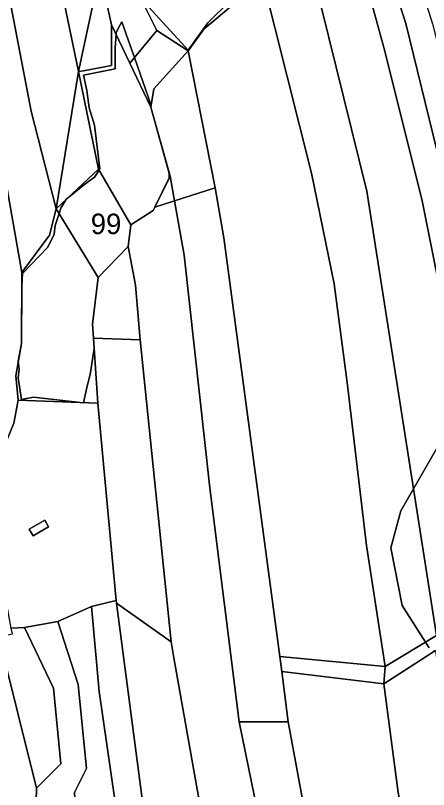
# Model space of a CAD drawing. Extents: x -502026 to -497664, y -1143484 to -1138019.
# Drawn here: x -499381.8 to -499220.8, y -1140133.9 to -1139831.7 of the extents above; entities that cross this region are included whole.
import ezdxf

# ---------------------------------------------------------------- set-up
doc = ezdxf.new("R2010")
doc.units = 0
for name, color, linetype in [('25', 7, 'Continuous'), ('31', 7, 'Continuous'), ('37', 7, 'Continuous'), ('43', 7, 'Continuous'), ('55', 7, 'Continuous'), ('62', 7, 'Continuous'), ('7', 7, 'Continuous')]:
    doc.layers.add(name, color=color, linetype=linetype)

msp = doc.modelspace()

# ---------------------------------------------------------------- linework, layer by layer
at = {"layer": '25'}
msp.add_lwpolyline([(-499275.49, -1140107.46), (-499268.89, -1140143.37), (-499257.79, -1140186.68), (-499277.97, -1140188.93), (-499294.52, -1140107.43)], close=True, dxfattribs=at)
at = {"layer": '31'}
for points in [[(-499349.66, -1139983.08), (-499342.49, -1140060.03), (-499352.11, -1140062.42), (-499365.32, -1140068.27), (-499378.26, -1140070.59), (-499383.4, -1140070.89), (-499393.27, -1140017.22), (-499382.43, -1139990.82), (-499380.68, -1139981.87)], [(-499368.86, -1140031.32), (-499370.36, -1140028.72), (-499376.42, -1140032.22), (-499374.92, -1140034.82)]]:
    msp.add_lwpolyline(points, close=True, dxfattribs=at)
at = {"layer": '37'}
for points in [[(-499303.92, -1139898.93), (-499319.81, -1139904.04), (-499321.51, -1139894.4), (-499328.94, -1139867.55), (-499327.8, -1139860.27), (-499314.46, -1139845.56)], [(-499319.81, -1139904.04), (-499327.5, -1139906.51), (-499321.51, -1139894.4)], [(-499333.13, -1139958.35), (-499351.39, -1139957.72), (-499351.77, -1139952.17), (-499349.52, -1139933.94), (-499337.88, -1139921.84), (-499334.94, -1139937)], [(-499333.13, -1139958.35), (-499321.12, -1140076.23), (-499342.35, -1140061.12), (-499342.49, -1140060.03), (-499349.66, -1139983.08), (-499351.39, -1139957.72)], [(-499175.16, -1140286.65), (-499173.86, -1140291.43), (-499164.43, -1140325.93), (-499181.73, -1140330.12), (-499177.24, -1140351.2), (-499198.42, -1140279.37), (-499205.65, -1140254.74), (-499215.6, -1140225.13), (-499224.19, -1140180), (-499232.57, -1140135.07), (-499238.14, -1140092.65), (-499218.01, -1140079.54), (-499208.2, -1140152.9), (-499200.42, -1140191.86), (-499195.81, -1140212.12), (-499192.03, -1140228.73), (-499184.85, -1140253.13)], [(-499238.14, -1140092.65), (-499232.57, -1140135.07), (-499224.19, -1140180), (-499215.6, -1140225.13), (-499205.65, -1140254.74), (-499198.42, -1140279.37), (-499177.24, -1140351.2), (-499181.86, -1140350.58), (-499186.12, -1140330.89), (-499194.15, -1140301.4), (-499232.59, -1140308.74), (-499240.39, -1140276.46), (-499257.79, -1140186.68), (-499268.89, -1140143.37), (-499275.49, -1140107.46), (-499277.96, -1140087.8)]]:
    msp.add_lwpolyline(points, close=True, dxfattribs=at)
at = {"layer": '43'}
msp.add_lwpolyline([(-499285.35, -1139817.65), (-499308.24, -1139836.91), (-499314.46, -1139845.56), (-499326.63, -1139837.6), (-499334.36, -1139822.12)], dxfattribs=at)
for points in [[(-499337.17, -1139850.27), (-499328.94, -1139867.55), (-499321.51, -1139894.4), (-499327.5, -1139906.51), (-499328.13, -1139907.79), (-499336.82, -1139913.47), (-499349.41, -1139891.67), (-499357.18, -1139853.6), (-499355.29, -1139853.26), (-499344.29, -1139851.25), (-499344.29, -1139835.32)], [(-499336.82, -1139913.47), (-499337.88, -1139921.84), (-499349.52, -1139933.94), (-499365.9, -1139907.16), (-499349.41, -1139891.67)], [(-499349.52, -1139933.94), (-499351.77, -1139952.17), (-499351.39, -1139957.72), (-499349.66, -1139983.08), (-499380.68, -1139981.87), (-499381.67, -1139972.31), (-499379.47, -1139959.8), (-499379.32, -1139932.04), (-499368.48, -1139917.4), (-499365.9, -1139907.16)], [(-499357.37, -1140158.51), (-499365.32, -1140171.39), (-499369.48, -1140189.57), (-499363.93, -1140210.02), (-499359.89, -1140229.53), (-499370.27, -1140214.75), (-499371, -1140201.82), (-499375.55, -1140186.57), (-499378.31, -1140154.18), (-499373.9, -1140148.81), (-499373.55, -1140133.33), (-499364.06, -1140123.86), (-499366.96, -1140094.25), (-499378.26, -1140070.59), (-499365.32, -1140068.27), (-499357.31, -1140092.81), (-499354.09, -1140125.66), (-499358.76, -1140135)]]:
    msp.add_lwpolyline(points, close=True, dxfattribs=at)
at = {"layer": '55'}
for points in [[(-499335.19, -1139789.66), (-499331.93, -1139812.11), (-499334.36, -1139822.12), (-499326.63, -1139837.6), (-499337.17, -1139850.27), (-499344.29, -1139835.32), (-499348.85, -1139814.64), (-499339.35, -1139770.23)], [(-499344.29, -1139835.32), (-499344.29, -1139851.25), (-499355.29, -1139853.26), (-499357.18, -1139853.6), (-499348.85, -1139814.64)], [(-499314.46, -1139845.56), (-499327.8, -1139860.27), (-499328.94, -1139867.55), (-499337.17, -1139850.27), (-499326.63, -1139837.6)], [(-499349.41, -1139891.67), (-499365.9, -1139907.16), (-499357.18, -1139853.6)], [(-499368.86, -1140031.32), (-499374.92, -1140034.82), (-499376.42, -1140032.22), (-499370.36, -1140028.72)], [(-499237.69, -1140085.86), (-499238.14, -1140092.65), (-499277.96, -1140087.8), (-499278.75, -1140081.89)]]:
    msp.add_lwpolyline(points, close=True, dxfattribs=at)
msp.add_lwpolyline([(-499218.01, -1140079.54), (-499238.14, -1140092.65), (-499237.69, -1140085.86), (-499217.66, -1140073.7)], dxfattribs=at)
at = {"layer": '62'}
for points in [[(-499332.69, -1139825.25), (-499314.44, -1139845.25), (-499306.78, -1139834.62), (-499289.78, -1139817.62)], [(-499289.78, -1139817.62), (-499306.78, -1139834.62), (-499314.44, -1139845.25), (-499332.69, -1139825.25)], [(-499220.5, -1140078.5), (-499221.91, -1140076.28), (-499231, -1140062), (-499235.5, -1140039.5), (-499231.5, -1140025), (-499226.61, -1140016.51), (-499217.09, -1140000)], [(-499217.09, -1140000), (-499226.61, -1140016.51), (-499231.5, -1140025), (-499235.5, -1140039.5), (-499231, -1140062), (-499221.91, -1140076.28), (-499220.5, -1140078.5)]]:
    msp.add_lwpolyline(points, dxfattribs=at)
for points in [[(-499337.1, -1139843.35), (-499340.34, -1139834.12), (-499340.98, -1139835.39), (-499342.47, -1139838.37), (-499342.52, -1139839.04), (-499342.91, -1139844.37), (-499342.91, -1139852.5), (-499355.22, -1139855), (-499353.94, -1139861), (-499353.58, -1139863.89), (-499353.09, -1139867.75), (-499350.97, -1139874.5), (-499348.84, -1139891.5), (-499349.19, -1139892.05), (-499350.97, -1139894.87), (-499354.78, -1139897.5), (-499361.03, -1139902.59), (-499361.54, -1139903), (-499362, -1139903.37), (-499362.17, -1139903.66), (-499364.12, -1139906.87), (-499364.79, -1139908.98), (-499366.25, -1139913.62), (-499366.69, -1139917), (-499369.22, -1139922.12), (-499379, -1139932.37), (-499379.35, -1139936.94), (-499379.47, -1139959.8), (-499380.67, -1139966.63), (-499380.28, -1139969.75), (-499380.72, -1139973.12), (-499379.44, -1139981.62), (-499374.75, -1139980.75), (-499355.39, -1139982.86), (-499355.29, -1139982.86), (-499355.22, -1139982.86), (-499353.94, -1139976.87), (-499352.66, -1139971.87), (-499351.81, -1139966.75), (-499351.11, -1139961.76), (-499351.39, -1139957.72), (-499351.77, -1139952.17), (-499349.52, -1139933.94), (-499337.88, -1139921.84), (-499336.82, -1139913.47), (-499328.13, -1139907.79), (-499327.5, -1139906.51), (-499321.83, -1139895.05), (-499321.9, -1139893.66), (-499321.94, -1139892.85), (-499328.94, -1139867.55), (-499328.83, -1139866.84), (-499335.41, -1139848.15)], [(-499353.94, -1139976.87), (-499355.22, -1139982.86), (-499355.29, -1139982.86), (-499355.39, -1139982.86), (-499374.75, -1139980.75), (-499379.44, -1139981.62), (-499380.72, -1139973.12), (-499380.28, -1139969.75), (-499380.67, -1139966.63), (-499379.47, -1139959.8), (-499379.35, -1139936.94), (-499379, -1139932.37), (-499369.22, -1139922.12), (-499366.69, -1139917), (-499366.25, -1139913.62), (-499364.79, -1139908.98), (-499364.12, -1139906.87), (-499362.17, -1139903.66), (-499362, -1139903.37), (-499361.54, -1139903), (-499361.03, -1139902.59), (-499354.78, -1139897.5), (-499350.97, -1139894.87), (-499349.19, -1139892.05), (-499348.84, -1139891.5), (-499350.97, -1139874.5), (-499353.09, -1139867.75), (-499353.58, -1139863.89), (-499353.94, -1139861), (-499355.22, -1139855), (-499342.91, -1139852.5), (-499342.91, -1139844.37), (-499342.52, -1139839.04), (-499342.47, -1139838.37), (-499340.98, -1139835.39), (-499340.34, -1139834.12), (-499337.1, -1139843.35), (-499335.41, -1139848.15), (-499328.83, -1139866.84), (-499328.94, -1139867.55), (-499321.94, -1139892.85), (-499321.9, -1139893.66), (-499321.83, -1139895.05), (-499327.5, -1139906.51), (-499328.13, -1139907.79), (-499336.82, -1139913.47), (-499337.88, -1139921.84), (-499349.52, -1139933.94), (-499351.77, -1139952.17), (-499351.39, -1139957.72), (-499351.11, -1139961.76), (-499351.81, -1139966.75), (-499352.66, -1139971.87)]]:
    msp.add_lwpolyline(points, close=True, dxfattribs=at)
at = {"layer": '7'}
for points in [[(-499462.13, -1139392.32), (-499452.18, -1139431.77), (-499430, -1139542.05), (-499408.7, -1139631.01), (-499398.52, -1139677.52), (-499366.99, -1139806.44), (-499357.18, -1139853.6), (-499365.9, -1139907.16), (-499375.64, -1139869.1), (-499386.86, -1139810.63), (-499402.82, -1139746.67), (-499404.07, -1139741.68), (-499434.09, -1139621.39), (-499461.83, -1139476.75), (-499476.3, -1139410.22), (-499482.26, -1139375.44)], [(-499437.56, -1139413.79), (-499408.51, -1139551.73), (-499378.3, -1139675.67), (-499371.42, -1139712.23), (-499363.06, -1139748.52), (-499348.85, -1139814.64), (-499357.18, -1139853.6), (-499366.99, -1139806.44), (-499398.52, -1139677.52), (-499408.7, -1139631.01), (-499430, -1139542.05), (-499452.18, -1139431.77), (-499462.13, -1139392.32)], [(-499168.46, -1140054.39), (-499182.39, -1140057.99), (-499186.6, -1140031.86), (-499204.26, -1139941.85), (-499215.89, -1139890.68), (-499229.56, -1139834.82), (-499240.38, -1139801.08), (-499252.55, -1139752.75), (-499250.96, -1139751.79), (-499256.29, -1139734.32), (-499265.67, -1139686.78), (-499274.74, -1139657.5), (-499281.8, -1139605.93), (-499275.3, -1139595.11), (-499264.72, -1139657.69), (-499255.65, -1139684.59), (-499241.17, -1139744.27), (-499244.67, -1139747.33), (-499234.65, -1139785.92), (-499219.22, -1139834.99), (-499195.41, -1139929.12)], [(-499182.39, -1140057.99), (-499196.59, -1140062.55), (-499210.31, -1139968.61), (-499223.35, -1139903.35), (-499238.15, -1139844.22), (-499257.72, -1139772.84), (-499265.67, -1139738.27), (-499274.98, -1139693.06), (-499282.54, -1139663.26), (-499288.49, -1139634.86), (-499291.07, -1139621.36), (-499281.8, -1139605.93), (-499274.74, -1139657.5), (-499265.67, -1139686.78), (-499256.29, -1139734.32), (-499250.96, -1139751.79), (-499252.55, -1139752.75), (-499240.38, -1139801.08), (-499229.56, -1139834.82), (-499215.89, -1139890.68), (-499204.26, -1139941.85), (-499186.6, -1140031.86)], [(-499196.59, -1140062.55), (-499217.66, -1140073.7), (-499244.79, -1139900.32), (-499271.62, -1139791.8), (-499272.84, -1139773.2), (-499277.78, -1139766.14), (-499278.33, -1139764.48), (-499288.62, -1139725.89), (-499298.58, -1139673.8), (-499296.45, -1139664.36), (-499288.49, -1139634.86), (-499282.54, -1139663.26), (-499274.98, -1139693.06), (-499265.67, -1139738.27), (-499257.72, -1139772.84), (-499238.15, -1139844.22), (-499223.35, -1139903.35), (-499210.31, -1139968.61)], [(-499365.9, -1139907.16), (-499368.48, -1139917.4), (-499379.32, -1139932.04), (-499389.07, -1139877.11), (-499414.48, -1139775.83), (-499402.82, -1139746.67), (-499386.86, -1139810.63), (-499375.64, -1139869.1)], [(-499217.66, -1140073.7), (-499237.69, -1140085.86), (-499244.94, -1140038.64), (-499252.47, -1139974.99), (-499257.59, -1139936.39), (-499266.33, -1139893.28), (-499285.35, -1139817.65), (-499276.17, -1139808.39), (-499272.53, -1139795.8), (-499277.78, -1139766.14), (-499272.84, -1139773.2), (-499271.62, -1139791.8), (-499244.79, -1139900.32)], [(-499379.32, -1139932.04), (-499379.47, -1139959.8), (-499381.67, -1139972.31), (-499380.68, -1139981.87), (-499382.43, -1139990.82), (-499393.27, -1140017.22), (-499395.27, -1139982.34), (-499399.11, -1139942.16), (-499415.93, -1139850.38), (-499424.2, -1139800.13), (-499414.48, -1139775.83), (-499389.07, -1139877.11)], [(-499237.69, -1140085.86), (-499278.75, -1140081.89), (-499300.53, -1139918.49), (-499303.92, -1139898.93), (-499314.46, -1139845.56), (-499308.24, -1139836.91), (-499285.35, -1139817.65), (-499266.33, -1139893.28), (-499257.59, -1139936.39), (-499252.47, -1139974.99), (-499244.94, -1140038.64)], [(-499278.75, -1140081.89), (-499277.96, -1140087.8), (-499275.49, -1140107.46), (-499294.52, -1140107.43), (-499306.04, -1140016.03), (-499316.05, -1139925.32), (-499319.81, -1139904.04), (-499303.92, -1139898.93), (-499300.53, -1139918.49)], [(-499342.35, -1140061.12), (-499331.56, -1140143.48), (-499317.08, -1140215.68), (-499275.31, -1140380.63), (-499270.08, -1140400.91), (-499257.33, -1140448.28), (-499263.54, -1140450.42), (-499282.02, -1140394.66), (-499288.54, -1140366.65), (-499309.4, -1140299.49), (-499337.15, -1140168.8), (-499343.05, -1140137.93), (-499349.12, -1140095.6), (-499352.11, -1140062.42), (-499342.49, -1140060.03)], [(-499321.12, -1140076.23), (-499320.01, -1140082.5), (-499308.02, -1140149.83), (-499301.15, -1140189.25), (-499295.05, -1140216.66), (-499289.56, -1140253.92), (-499269.75, -1140325.57), (-499258.32, -1140375.79), (-499275.31, -1140380.63), (-499317.08, -1140215.68), (-499331.56, -1140143.48), (-499342.35, -1140061.12)], [(-499388.38, -1140074.3), (-499373.55, -1140133.33), (-499373.9, -1140148.81), (-499398.34, -1140149.97), (-499401.36, -1140131.25), (-499415.33, -1140064.26), (-499398.2, -1140071.67)], [(-499337.15, -1140168.8), (-499358.01, -1140169.13), (-499357.37, -1140158.51), (-499358.76, -1140135), (-499354.09, -1140125.66), (-499357.31, -1140092.81), (-499365.32, -1140068.27), (-499352.11, -1140062.42), (-499349.12, -1140095.6), (-499343.05, -1140137.93)], [(-499373.55, -1140133.33), (-499388.38, -1140074.3), (-499382.99, -1140073.11), (-499383.4, -1140070.89), (-499378.26, -1140070.59), (-499366.96, -1140094.25), (-499364.06, -1140123.86)]]:
    msp.add_lwpolyline(points, close=True, dxfattribs=at)
msp.add_lwpolyline([(-499269.75, -1140325.57), (-499289.56, -1140253.92), (-499295.05, -1140216.66), (-499301.15, -1140189.25), (-499308.02, -1140149.83), (-499320.01, -1140082.5), (-499321.12, -1140076.23), (-499333.13, -1139958.35), (-499334.94, -1139937), (-499337.88, -1139921.84), (-499336.82, -1139913.47), (-499328.13, -1139907.79), (-499327.5, -1139906.51), (-499319.81, -1139904.04), (-499316.05, -1139925.32), (-499306.04, -1140016.03), (-499294.52, -1140107.43), (-499277.97, -1140188.93), (-499270.05, -1140210.03), (-499264.59, -1140256.07), (-499249.65, -1140321.45), (-499246.16, -1140334.66)], dxfattribs=at)

# ---------------------------------------------------------------- texts
at = {"layer": '62'}
msp.add_text('99', height=8, dxfattribs=at).set_placement((-499352.42, -1139917.04))

doc.saveas('drawing.dxf')
